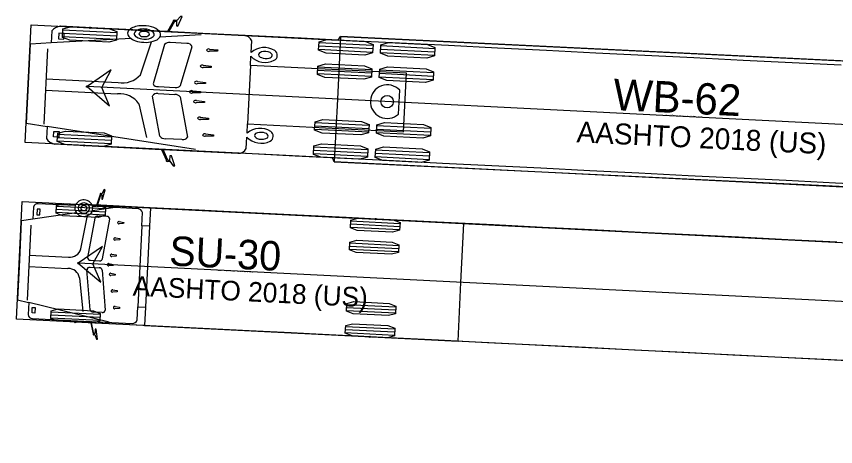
# Model space of a CAD drawing. Extents: x 260275 to 261282, y 610916 to 614143.
# Drawn here: x 260772.7 to 260828.3, y 612585.3 to 612614.4 of the extents above; entities that cross this region are included whole.
import ezdxf

# ---------------------------------------------------------------- set-up
doc = ezdxf.new("R2010")
doc.units = 0
doc.layers.add('TopoDOT_Transients', color=7, linetype='Continuous')

msp = doc.modelspace()

# ---------------------------------------------------------------- linework, layer by layer
at = {"layer": 'TopoDOT_Transients'}
for p, q in [((260783.548, 612614.144), (260783.566, 612614.163)), ((260783.548, 612614.118), (260783.548, 612614.144)), ((260780.365, 612613.542), (260775.67, 612613.777)), ((260775.841, 612613.539), (260779.503, 612613.356)), ((260780.468, 612612.938), (260775.055, 612612.642)), ((260775.568, 612613.306), (260775.55, 612612.928)), ((260775.55, 612612.928), (260775.905, 612612.91)), ((260775.924, 612613.288), (260775.568, 612613.306)), ((260775.818, 612613.081), (260779.48, 612612.898)), ((260775.829, 612613.31), (260779.492, 612613.127)), ((260775.905, 612612.91), (260775.924, 612613.288)), ((260785.23, 612613.198), (260782.43, 612613.045)), ((260773.623, 612612.563), (260773.354, 612607.199)), ((260781.1, 612610.483), (260781.849, 612612.724)), ((260782.742, 612612.536), (260781.963, 612609.877)), ((260784.248, 612612.612), (260783.119, 612612.669)), ((260783.831, 612609.754), (260784.609, 612612.412)), ((260788.613, 612612.003), (260788.652, 612612.777)), ((260793.208, 612612.441), (260796.87, 612612.257)), ((260793.219, 612612.669), (260796.881, 612612.486)), ((260797.414, 612612.46), (260801.076, 612612.276)), ((260774.809, 612612.238), (260774.554, 612607.139)), ((260786.341, 612612.083), (260785.791, 612612.075)), ((260785.798, 612612.229), (260786.345, 612612.165)), ((260786.345, 612612.165), (260786.341, 612612.083)), ((260793.196, 612612.212), (260796.858, 612612.028)), ((260797.391, 612612.002), (260801.053, 612611.819)), ((260797.402, 612612.231), (260801.065, 612612.047)), ((260785.9, 612610.986), (260785.35, 612610.978)), ((260785.357, 612611.132), (260785.904, 612611.069)), ((260785.904, 612611.069), (260785.9, 612610.986)), ((260788.569, 612611.116), (260788.37, 612607.147)), ((260793.125, 612610.793), (260796.787, 612610.609)), ((260793.137, 612611.021), (260796.799, 612610.838)), ((260797.331, 612610.812), (260800.994, 612610.628)), ((260774.707, 612610.203), (260779.593, 612609.959)), ((260793.114, 612610.564), (260796.776, 612610.38)), ((260797.309, 612610.354), (260800.971, 612610.171)), ((260797.32, 612610.583), (260800.982, 612610.399)), ((260950.706, 612601.011), (260777.483, 612609.681)), ((260782.324, 612609.677), (260783.453, 612609.621)), ((260785.511, 612609.887), (260784.96, 612609.879)), ((260784.968, 612610.033), (260785.515, 612609.97)), ((260785.515, 612609.97), (260785.511, 612609.887)), ((260774.669, 612609.439), (260779.555, 612609.194)), ((260782.43, 612606.316), (260781.921, 612609.039)), ((260782.3, 612609.202), (260783.429, 612609.146)), ((260783.792, 612608.976), (260784.301, 612606.253)), ((260785.17, 612609.255), (260784.619, 612609.247)), ((260784.627, 612609.401), (260785.174, 612609.338)), ((260785.174, 612609.338), (260785.17, 612609.255)), ((260798.613, 612607.815), (260798.694, 612609.429)), ((260781.002, 612608.522), (260781.521, 612606.23)), ((260785.446, 612608.592), (260784.895, 612608.584)), ((260784.903, 612608.738), (260785.45, 612608.675)), ((260785.45, 612608.675), (260785.446, 612608.592)), ((260785.724, 612607.46), (260785.148, 612607.452)), ((260785.156, 612607.606), (260785.728, 612607.542)), ((260785.728, 612607.542), (260785.724, 612607.46)), ((260784.84, 612605.408), (260774.772, 612606.978)), ((260792.925, 612606.785), (260796.587, 612606.602)), ((260792.936, 612607.014), (260796.598, 612606.831)), ((260792.948, 612607.243), (260796.61, 612607.06)), ((260797.131, 612606.804), (260800.793, 612606.621)), ((260797.142, 612607.033), (260800.804, 612606.85)), ((260775.216, 612606.266), (260775.235, 612606.644)), ((260775.572, 612606.248), (260775.216, 612606.266)), ((260775.235, 612606.644), (260775.591, 612606.626)), ((260775.475, 612606.236), (260779.138, 612606.052)), ((260775.487, 612606.464), (260779.149, 612606.281)), ((260775.591, 612606.626), (260775.572, 612606.248)), ((260786.053, 612606.325), (260785.502, 612606.316)), ((260785.51, 612606.471), (260786.057, 612606.407)), ((260786.057, 612606.407), (260786.053, 612606.325)), ((260788.287, 612605.486), (260788.326, 612606.26)), ((260797.119, 612606.575), (260800.782, 612606.392)), ((260775.464, 612606.007), (260779.126, 612605.823)), ((260783.922, 612606.09), (260782.793, 612606.146)), ((260792.842, 612605.137), (260796.504, 612604.954)), ((260792.854, 612605.366), (260796.516, 612605.183)), ((260792.865, 612605.595), (260796.527, 612605.412)), ((260797.048, 612605.156), (260800.711, 612604.973)), ((260797.06, 612605.385), (260800.722, 612605.202)), ((260783.075, 612604.661), (260783.072, 612604.636)), ((260783.072, 612604.636), (260783.088, 612604.614)), ((260797.037, 612604.927), (260800.699, 612604.744)), ((260776.683, 612601.611), (260774.163, 612601.737)), ((260774.103, 612601.364), (260774.084, 612600.986)), ((260774.297, 612601.355), (260774.103, 612601.364)), ((260774.278, 612600.976), (260774.297, 612601.355)), ((260775.398, 612601.358), (260778.727, 612601.192)), ((260775.409, 612601.566), (260778.738, 612601.4)), ((260779.382, 612601.476), (260777.848, 612601.26)), ((260776.773, 612601.108), (260773.807, 612600.689)), ((260774.084, 612600.986), (260774.278, 612600.976)), ((260775.388, 612601.15), (260778.717, 612600.984)), ((260777.063, 612598.67), (260777.523, 612600.926)), ((260778.007, 612600.758), (260777.521, 612598.084)), ((260778.832, 612600.868), (260778.216, 612600.899)), ((260778.539, 612598.003), (260779.024, 612600.677)), ((260773.664, 612600.28), (260773.409, 612595.181)), ((260779.964, 612600.387), (260779.663, 612600.366)), ((260779.67, 612600.52), (260779.968, 612600.469)), ((260779.968, 612600.469), (260779.964, 612600.387)), ((260781.197, 612600.23), (260780.923, 612594.745)), ((260781.728, 612600.203), (260781.454, 612594.718)), ((260795.363, 612600.15), (260798.692, 612599.984)), ((260795.373, 612600.359), (260798.702, 612600.192)), ((260795.384, 612600.567), (260798.713, 612600.4)), ((260779.698, 612599.282), (260779.397, 612599.261)), ((260779.404, 612599.415), (260779.702, 612599.364)), ((260779.702, 612599.364), (260779.698, 612599.282)), ((260795.309, 612599.069), (260798.638, 612598.902)), ((260795.288, 612598.652), (260798.617, 612598.486)), ((260795.298, 612598.86), (260798.627, 612598.694)), ((260773.562, 612598.246), (260776.227, 612598.112)), ((260777.713, 612597.893), (260778.329, 612597.862)), ((260779.46, 612598.175), (260779.159, 612598.154)), ((260779.166, 612598.308), (260779.464, 612598.257)), ((260779.464, 612598.257), (260779.46, 612598.175)), ((260773.524, 612597.481), (260776.189, 612597.348)), ((261025.504, 612585.252), (260776.884, 612597.696)), ((260777.69, 612597.418), (260778.306, 612597.387)), ((260779.259, 612597.536), (260778.958, 612597.515)), ((260778.966, 612597.669), (260779.264, 612597.618)), ((260779.264, 612597.618), (260779.259, 612597.536)), ((260777.695, 612594.538), (260777.479, 612597.246)), ((260778.5, 612597.225), (260778.716, 612594.517)), ((260779.395, 612596.88), (260779.094, 612596.859)), ((260779.102, 612597.013), (260779.399, 612596.963)), ((260779.399, 612596.963), (260779.395, 612596.88)), ((260776.965, 612596.709), (260777.196, 612594.431)), ((260779.521, 612595.755), (260779.206, 612595.734)), ((260779.214, 612595.888), (260779.525, 612595.838)), ((260779.525, 612595.838), (260779.521, 612595.755)), ((260778.992, 612593.686), (260773.524, 612595.026)), ((260773.751, 612594.324), (260773.77, 612594.702)), ((260773.77, 612594.702), (260773.964, 612594.693)), ((260773.964, 612594.693), (260773.945, 612594.314)), ((260779.676, 612594.629), (260779.374, 612594.608)), ((260779.382, 612594.762), (260779.68, 612594.711)), ((260779.68, 612594.711), (260779.676, 612594.629)), ((260795.09, 612594.699), (260798.419, 612594.532)), ((260795.1, 612594.907), (260798.429, 612594.74)), ((260773.945, 612594.314), (260773.751, 612594.324)), ((260775.029, 612593.993), (260778.359, 612593.826)), ((260775.04, 612594.201), (260778.369, 612594.034)), ((260775.05, 612594.409), (260778.379, 612594.242)), ((260778.505, 612594.346), (260777.889, 612594.376)), ((260795.079, 612594.491), (260798.409, 612594.324)), ((260795.025, 612593.409), (260798.354, 612593.242)), ((260795.004, 612592.993), (260798.334, 612592.826)), ((260795.015, 612593.201), (260798.344, 612593.034))]:
    msp.add_line(p, q, dxfattribs=at)
for points in [[(260783.343, 612614.133), (260782.938, 612613.413), (260782.365, 612613.442)], [(260788.113, 612613.154), (260783.037, 612613.408), (260783.429, 612614.112), (260783.429, 612614.112)], [(260783.466, 612614.121), (260783.548, 612614.118), (260783.548, 612613.797), (260783.651, 612613.792), (260783.941, 612614.44), (260783.821, 612614.446), (260783.566, 612614.163), (260783.479, 612614.167)], [(260919.365, 612598.455), (260908.692, 612598.918), (260887.354, 612599.929), (260794.257, 612604.583), (260794.126, 612604.843), (260773.289, 612605.886), (260773.688, 612613.876), (260794.522, 612612.834), (260794.667, 612613.073), (260858.102, 612610.013), (260879.417, 612609.02), (260900.73, 612608.077), (260911.385, 612607.632), (260922.039, 612607.21)], [(260775.096, 612613.455), (260775.055, 612612.642), (260773.635, 612612.564)], [(260828.65, 612611.125), (260825.319, 612611.292), (260821.988, 612611.459), (260818.657, 612611.625), (260815.326, 612611.792), (260811.995, 612611.959), (260808.663, 612612.126), (260805.332, 612612.292), (260802.001, 612612.459), (260798.67, 612612.626), (260795.339, 612612.793), (260792.008, 612612.959), (260788.676, 612613.126), (260785.345, 612613.293), (260782.014, 612613.459), (260778.683, 612613.626), (260777.683, 612613.676)], [(260842.54, 612610.734), (260842.541, 612610.756), (260794.667, 612613.073), (260794.462, 612608.828), (260794.257, 612604.583), (260842.13, 612602.266), (260842.131, 612602.289)], [(260773.623, 612612.563), (260773.354, 612607.199), (260774.772, 612606.978), (260774.731, 612606.164)], [(260788.339, 612606.518), (260788.37, 612607.147), (260798.957, 612606.617), (260799.156, 612610.586), (260788.569, 612611.116), (260788.601, 612611.745)], [(260777.483, 612609.681), (260779.007, 612608.386), (260778.482, 612609.631), (260779.129, 612610.818), (260777.483, 612609.681)], [(260775.27, 612605.787), (260782.538, 612605.423), (260782.87, 612604.667)], [(260831.583, 612602.968), (260828.252, 612603.135), (260824.92, 612603.302), (260821.589, 612603.469), (260818.258, 612603.635), (260814.927, 612603.802), (260811.595, 612603.969), (260808.264, 612604.136), (260804.933, 612604.302), (260801.602, 612604.469), (260798.27, 612604.636), (260794.939, 612604.803), (260791.608, 612604.969), (260788.277, 612605.136), (260784.945, 612605.303), (260781.614, 612605.469), (260778.283, 612605.636), (260777.284, 612605.686)], [(260782.957, 612604.679), (260782.957, 612604.679), (260782.638, 612605.418), (260787.713, 612605.164)], [(260783.001, 612604.62), (260783.088, 612604.614), (260783.314, 612604.308), (260783.434, 612604.302), (260783.21, 612604.975), (260783.107, 612604.981), (260783.075, 612604.661), (260782.993, 612604.666)], [(260778.371, 612602.367), (260778.371, 612602.366), (260778.104, 612601.547), (260778.092, 612601.541), (260777.864, 612601.552)], [(260780.94, 612601.398), (260778.169, 612601.537), (260778.158, 612601.542), (260778.418, 612602.347), (260778.418, 612602.348)], [(260778.439, 612602.358), (260778.483, 612602.356), (260778.483, 612602.356), (260778.476, 612602.038), (260778.476, 612602.036), (260778.532, 612602.033), (260778.533, 612602.036), (260778.705, 612602.684), (260778.705, 612602.687), (260778.64, 612602.69), (260778.494, 612602.402), (260778.494, 612602.402), (260778.446, 612602.404)], [(260935.769, 612585.699), (260893.177, 612587.866), (260772.689, 612593.901), (260773.089, 612601.891), (260900.569, 612595.515), (260943.182, 612593.414)], [(260773.848, 612601.499), (260773.808, 612600.693), (260773.803, 612600.688), (260773.025, 612600.579), (260773.021, 612600.537), (260772.889, 612597.896), (260772.756, 612595.256), (260772.756, 612595.214), (260773.519, 612595.027), (260773.524, 612595.022), (260773.483, 612594.215)], [(260828.339, 612599.126), (260825.01, 612599.292), (260821.682, 612599.459), (260818.354, 612599.626), (260815.026, 612599.792), (260811.697, 612599.959), (260808.369, 612600.125), (260805.041, 612600.292), (260801.713, 612600.458), (260798.384, 612600.625), (260795.056, 612600.792), (260791.728, 612600.958), (260788.4, 612601.125), (260785.071, 612601.291), (260781.743, 612601.458), (260778.415, 612601.625), (260777.084, 612601.691)], [(260780.878, 612593.846), (260780.923, 612594.741), (260780.927, 612594.744), (260781.453, 612594.718), (260781.453, 612594.707), (260781.391, 612593.466), (260802.651, 612592.401), (260802.851, 612596.396), (260803.051, 612600.391), (260781.791, 612601.456), (260781.729, 612600.214), (260781.728, 612600.203), (260781.201, 612600.23), (260781.198, 612600.233), (260781.242, 612601.128)], [(260828.344, 612599.125), (260825.016, 612599.292), (260821.688, 612599.459), (260818.359, 612599.625), (260815.031, 612599.792), (260811.703, 612599.958), (260808.375, 612600.125), (260805.046, 612600.292), (260801.718, 612600.458), (260798.39, 612600.625), (260797.059, 612600.691)], [(260776.884, 612597.696), (260778.407, 612596.401), (260777.882, 612597.646), (260778.529, 612598.833), (260776.884, 612597.696)], [(260773.773, 612593.947), (260777.702, 612593.75), (260777.713, 612593.743), (260777.898, 612592.901), (260777.898, 612592.9)], [(260831.267, 612590.969), (260827.939, 612591.136), (260824.61, 612591.302), (260821.282, 612591.469), (260817.954, 612591.636), (260814.626, 612591.802), (260811.297, 612591.969), (260807.969, 612592.135), (260804.641, 612592.302), (260801.313, 612592.468), (260797.984, 612592.635), (260794.656, 612592.802), (260791.328, 612592.968), (260788, 612593.135), (260784.671, 612593.301), (260781.343, 612593.468), (260778.015, 612593.635), (260776.684, 612593.701)], [(260777.946, 612592.915), (260777.946, 612592.915), (260777.767, 612593.742), (260777.78, 612593.746), (260780.55, 612593.608)], [(260777.969, 612592.856), (260778.016, 612592.853), (260778.016, 612592.853), (260778.133, 612592.552), (260778.198, 612592.549), (260778.198, 612592.551), (260778.091, 612593.213), (260778.09, 612593.217), (260778.035, 612593.219), (260778.034, 612593.217), (260778.01, 612592.9), (260778.01, 612592.9), (260777.965, 612592.903)], [(260831.272, 612590.969), (260827.944, 612591.135), (260824.616, 612591.302), (260821.288, 612591.469), (260817.959, 612591.635), (260814.631, 612591.802), (260811.303, 612591.968), (260807.975, 612592.135), (260804.646, 612592.302), (260801.318, 612592.468), (260797.99, 612592.635), (260796.659, 612592.701)]]:
    msp.add_lwpolyline(points, dxfattribs=at)
for points in [[(260775.815, 612613.024), (260775.844, 612613.596), (260776.365, 612613.742), (260779.002, 612613.61), (260779.506, 612613.412), (260779.477, 612612.841), (260778.956, 612612.695), (260776.319, 612612.827)], [(260793.193, 612612.155), (260793.222, 612612.726), (260793.743, 612612.873), (260796.38, 612612.741), (260796.884, 612612.543), (260796.855, 612611.972), (260796.334, 612611.825), (260793.697, 612611.957)], [(260797.388, 612611.945), (260797.417, 612612.516), (260797.938, 612612.663), (260800.575, 612612.531), (260801.079, 612612.333), (260801.05, 612611.762), (260800.529, 612611.615), (260797.892, 612611.747)], [(260793.111, 612610.507), (260793.14, 612611.078), (260793.661, 612611.225), (260796.298, 612611.093), (260796.802, 612610.895), (260796.773, 612610.324), (260796.252, 612610.177), (260793.615, 612610.309)], [(260777.483, 612609.681), (260779.007, 612608.386), (260778.482, 612609.631), (260779.129, 612610.818)], [(260797.306, 612610.297), (260797.334, 612610.868), (260797.856, 612611.015), (260800.492, 612610.883), (260800.996, 612610.685), (260800.968, 612610.114), (260800.446, 612609.967), (260797.81, 612610.099)], [(260792.922, 612606.728), (260792.95, 612607.3), (260793.472, 612607.446), (260796.108, 612607.314), (260796.613, 612607.116), (260796.584, 612606.545), (260796.063, 612606.399), (260793.426, 612606.531)], [(260797.117, 612606.518), (260797.145, 612607.09), (260797.667, 612607.236), (260800.303, 612607.104), (260800.807, 612606.907), (260800.779, 612606.335), (260800.257, 612606.189), (260797.621, 612606.321)], [(260775.461, 612605.95), (260775.49, 612606.521), (260776.011, 612606.668), (260778.648, 612606.536), (260779.152, 612606.338), (260779.123, 612605.767), (260778.602, 612605.62), (260775.965, 612605.752)], [(260792.839, 612605.08), (260792.868, 612605.652), (260793.389, 612605.798), (260796.026, 612605.666), (260796.53, 612605.468), (260796.502, 612604.897), (260795.98, 612604.751), (260793.343, 612604.883)], [(260797.034, 612604.871), (260797.063, 612605.442), (260797.584, 612605.588), (260800.221, 612605.456), (260800.725, 612605.259), (260800.696, 612604.687), (260800.175, 612604.541), (260797.538, 612604.673)], [(260775.385, 612601.099), (260775.411, 612601.618), (260775.885, 612601.751), (260778.282, 612601.631), (260778.74, 612601.451), (260778.714, 612600.932), (260778.24, 612600.799), (260775.843, 612600.919)], [(260795.36, 612600.099), (260795.386, 612600.618), (260795.86, 612600.751), (260798.257, 612600.631), (260798.715, 612600.452), (260798.689, 612599.932), (260798.215, 612599.799), (260795.818, 612599.919)], [(260795.285, 612598.601), (260795.311, 612599.12), (260795.785, 612599.253), (260798.182, 612599.133), (260798.64, 612598.953), (260798.614, 612598.434), (260798.14, 612598.301), (260795.743, 612598.421)], [(260776.884, 612597.696), (260778.407, 612596.401), (260777.882, 612597.646), (260778.529, 612598.833)], [(260795.077, 612594.439), (260795.103, 612594.959), (260795.577, 612595.092), (260797.974, 612594.972), (260798.432, 612594.792), (260798.406, 612594.273), (260797.932, 612594.14), (260795.535, 612594.26)], [(260775.027, 612593.941), (260775.053, 612594.46), (260775.527, 612594.593), (260777.924, 612594.474), (260778.382, 612594.294), (260778.356, 612593.774), (260777.882, 612593.641), (260775.485, 612593.761)], [(260795.002, 612592.941), (260795.028, 612593.461), (260795.502, 612593.594), (260797.899, 612593.474), (260798.357, 612593.294), (260798.331, 612592.775), (260797.857, 612592.641), (260795.46, 612592.761)]]:
    msp.add_lwpolyline(points, close=True, dxfattribs=at)
for centre, radius in [((260777.683, 612613.676), 0.0417), ((260777.483, 612609.681), 0.0417), ((260797.846, 612608.664), 0.424), ((260777.284, 612605.686), 0.0417), ((260777.266, 612601.437), 0.374), ((260777.084, 612601.691), 0.0417), ((260777.266, 612601.437), 0.193), ((260797.059, 612600.691), 0.0417), ((260776.884, 612597.696), 0.0417), ((260776.684, 612593.701), 0.0417), ((260796.659, 612592.701), 0.0417)]:
    msp.add_circle(centre, radius, dxfattribs=at)
for centre, radius, start, end in [((260783.357, 612614.153), 0.0244, 122.9536, 236.268), ((260783.406, 612614.063), 0.127, 55.031, 119.2402), ((260783.421, 612614.222), 0.11, 274.0798, 294.1881), ((260775.735, 612612.988), 0.792, 94.669, 143.8245), ((260780.563, 612613.281), 0.328, 127.2239, 176.1283), ((260780.863, 612613.024), 0.719, 105.666, 133.923), ((260781.225, 612612.077), 1.731, 93.5207, 108.7185), ((260781.058, 612613.15), 0.407, 98.3662, 161.1706), ((260781.304, 612612.357), 1.234, 86.7653, 104.3474), ((260781.21, 612613.189), 0.22, 98.1455, 159.8437), ((260781.271, 612611.606), 2.204, 74.3347, 93.9698), ((260781.329, 612612.793), 0.631, 60.9439, 103.7444), ((260781.385, 612612.676), 0.913, 50.4452, 90.7055), ((260781.679, 612612.823), 0.924, 42.0327, 78.3109), ((260782.177, 612613.207), 0.301, 327.3669, 51.2652), ((260780.616, 612613.306), 0.38, 180.466, 230.9895), ((260781.087, 612613.816), 1.074, 228.5922, 252.8611), ((260780.939, 612613.292), 0.268, 182.2082, 245.8859), ((260781.372, 612614.002), 1.098, 240.4014, 268.294), ((260781.26, 612613.349), 0.27, 198.2845, 271.0283), ((260781.378, 612613.686), 0.617, 259.4232, 292.614), ((260781.436, 612613.814), 0.914, 263.97, 306.028), ((260781.59, 612613.234), 0.12, 282.1117, 67.5897), ((260781.843, 612613.225), 0.199, 310.9389, 51.5782), ((260781.799, 612613.535), 0.799, 282.935, 322.2027), ((260788.115, 612612.583), 0.571, 19.8286, 90.2202), ((260781.42, 612614.734), 2.049, 251.5166, 267.4419), ((260781.442, 612614.695), 2.012, 266.777, 285.4599), ((260783.047, 612612.272), 0.403, 79.6779, 139.1359), ((260784.303, 612612.28), 0.334, 23.4005, 95.9984), ((260789.497, 612610.99), 1.344, 57.5454, 131.1002), ((260785.747, 612612.043), 0.192, 74.5853, 142.0599), ((260785.758, 612612.264), 0.192, 212.1839, 279.7132), ((260789.58, 612612.665), 1.344, 223.171, 296.7258), ((260789.383, 612611.747), 0.29, 103.3313, 159.4913), ((260789.356, 612611.887), 0.247, 188.8529, 258.732), ((260789.547, 612611.201), 0.86, 65.6002, 105.5696), ((260789.798, 612611.877), 0.262, 276.8184, 343.3436), ((260789.824, 612611.77), 0.228, 7.9385, 69.8333), ((260790.007, 612611.804), 0.383, 297.6064, 56.6648), ((260789.613, 612612.469), 0.879, 249.6725, 284.2677), ((260785.306, 612610.947), 0.192, 74.5853, 142.0599), ((260785.317, 612611.167), 0.192, 212.1839, 279.7132), ((260779.88, 612611.564), 1.631, 259.869, 318.4598), ((260782.271, 612610.018), 0.342, 205.6073, 275.5338), ((260783.529, 612610.012), 0.397, 261.2114, 319.3744), ((260784.916, 612609.848), 0.192, 74.5853, 142.0599), ((260784.927, 612610.068), 0.192, 212.1839, 279.7132), ((260797.846, 612608.662), 1.143, 42.1356, 312.1356), ((260779.68, 612607.568), 1.631, 35.8114, 94.4022), ((260782.214, 612608.868), 0.342, 78.7374, 148.6639), ((260783.466, 612608.749), 0.397, 34.8968, 93.0598), ((260784.576, 612609.216), 0.192, 74.5853, 142.0599), ((260784.587, 612609.436), 0.192, 212.2113, 279.6859), ((260784.852, 612608.553), 0.192, 74.558, 142.0873), ((260784.863, 612608.774), 0.192, 212.2113, 279.6859), ((260785.13, 612607.421), 0.192, 74.558, 142.0873), ((260785.141, 612607.641), 0.192, 212.2113, 279.6859), ((260789.222, 612605.505), 1.344, 57.5454, 131.1002), ((260782.76, 612606.548), 0.403, 215.1353, 274.5933), ((260784.009, 612606.415), 0.334, 258.2728, 330.8707), ((260785.459, 612606.285), 0.192, 74.558, 142.0873), ((260785.47, 612606.506), 0.192, 212.2113, 279.6859), ((260789.306, 612607.18), 1.344, 223.171, 296.7258), ((260789.076, 612606.302), 0.247, 95.5392, 165.4183), ((260789.118, 612606.438), 0.29, 194.7799, 250.9399), ((260789.274, 612605.697), 0.879, 70.0035, 104.5987), ((260789.518, 612606.267), 0.262, 10.9276, 77.4528), ((260789.553, 612606.371), 0.228, 284.4379, 346.3327), ((260789.725, 612606.319), 0.387, 298.6311, 55.6401), ((260775.413, 612606.565), 0.792, 210.4467, 259.6022), ((260789.335, 612606.964), 0.86, 248.7016, 288.671), ((260787.772, 612605.732), 0.571, 264.051, 334.4426), ((260782.881, 612604.645), 0.0244, 118.0032, 231.3176), ((260782.939, 612604.731), 0.127, 235.031, 299.2402), ((260782.938, 612604.571), 0.11, 60.0831, 80.1914), ((260778.409, 612602.384), 0.0418, 27.6277, 204.6426), ((260778.41, 612602.39), 0.0434, 281.048, 311.7208), ((260774.127, 612601.458), 0.282, 82.5067, 171.5861), ((260777.263, 612601.37), 0.628, 16.8878, 157.3795), ((260777.18, 612601.441), 0.526, 161.0797, 219.3257), ((260777.353, 612601.432), 0.524, 319.3935, 13.1936), ((260780.924, 612601.076), 0.323, 9.2861, 87.1345), ((260777.261, 612601.505), 0.629, 219.1801, 267.8694), ((260777.276, 612601.505), 0.63, 266.4893, 318.8921), ((260778.193, 612600.708), 0.193, 83.0776, 164.9921), ((260778.84, 612600.684), 0.184, 357.7271, 92.5983), ((260779.647, 612600.432), 0.091, 75.4511, 169.6149), ((260779.649, 612600.456), 0.0909, 184.6184, 278.8536), ((260779.382, 612599.327), 0.091, 75.4511, 169.6149), ((260779.383, 612599.351), 0.0909, 184.6184, 278.8536), ((260776.319, 612598.88), 0.773, 263.1599, 344.244), ((260777.705, 612598.077), 0.184, 177.7326, 272.5928), ((260778.353, 612598.053), 0.193, 263.0727, 344.997), ((260779.144, 612598.22), 0.091, 75.4511, 169.6149), ((260779.145, 612598.244), 0.0909, 184.6184, 278.8536), ((260776.204, 612596.575), 0.773, 10.025, 91.1091), ((260777.663, 612597.235), 0.184, 81.6762, 176.5364), ((260778.31, 612597.194), 0.193, 9.272, 91.1963), ((260778.943, 612597.581), 0.091, 75.4511, 169.6149), ((260778.944, 612597.605), 0.091, 184.6541, 278.8179), ((260779.079, 612596.925), 0.0909, 75.4154, 169.6506), ((260779.08, 612596.949), 0.091, 184.6541, 278.8179), ((260779.205, 612595.801), 0.0909, 75.4154, 169.6506), ((260779.206, 612595.824), 0.091, 184.6541, 278.8179), ((260777.885, 612594.569), 0.193, 189.2769, 271.1914), ((260778.532, 612594.528), 0.184, 261.6707, 356.5419), ((260779.359, 612594.674), 0.0909, 75.4154, 169.6506), ((260779.36, 612594.698), 0.091, 184.6541, 278.8179), ((260773.765, 612594.228), 0.282, 182.6829, 271.7623), ((260780.566, 612593.93), 0.323, 267.1345, 344.9829), ((260777.934, 612592.879), 0.0418, 149.6264, 326.6414), ((260777.933, 612592.873), 0.0434, 42.5482, 73.221)]:
    msp.add_arc(centre, radius, start, end, dxfattribs=at)
for centre, major_axis, start_param, end_param in [((260783.41, 612614.151), (0.0781, -0.0039), 3.71124, 4.981984), ((260783.41, 612614.151), (-0.0781, 0.0039), 2.398717, 3.668019), ((260782.934, 612604.643), (-0.0781, 0.0039), 4.442794, 5.713538), ((260782.934, 612604.643), (0.0781, -0.0039), 5.756759, 7.026061)]:
    msp.add_ellipse(centre, major_axis=major_axis, ratio=0.5, start_param=start_param, end_param=end_param, dxfattribs=at)

# ---------------------------------------------------------------- texts
for s, height, rotation, p in [('WB-62', 2.125, 357.23, (260813.136, 612608.094)), ('AASHTO 2018 (US)', 1.41667, 357.23, (260810.675, 612605.909)), ('(c) 2023 Transoft Solutions, Inc. All rights reserved.', 0.085, 357.23, (260816.693, 612607.709)), ('SU-30', 2, 357.1345, (260783.027, 612597.549)), ('AASHTO 2018 (US)', 1.33333, 357.1345, (260780.564, 612595.503)), ('(c) 2023 Transoft Solutions, Inc. All rights reserved.', 0.08, 357.1345, (260786.232, 612597.188))]:
    msp.add_text(s, height=height, rotation=rotation, dxfattribs=at).set_placement(p)

doc.saveas('drawing.dxf')
